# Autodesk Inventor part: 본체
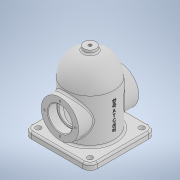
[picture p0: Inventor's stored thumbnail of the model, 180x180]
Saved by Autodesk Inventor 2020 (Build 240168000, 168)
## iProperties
Created: 2021-07
Part Number: 본체
Material: 일반
Document SubType Name: Modeling
Designer: Owner
Density: 1 g/cm^3
Appearance: 기본값
Author: Owner
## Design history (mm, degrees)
sketch "스케치1"
  geometry: C1 r 40 at (0, 0); 1 further point
  constraints: 1 centre point, 1 coincident
  dimensions: "d0" = 80 diameter of C1
extrude "돌출1" new body sketch "스케치1" distance "d1" = 124; taper "d2" = 0 deg
fillet "모깎기1" dims "d3" = 40
feature "쉘1" dims "d4" = 8
node "작업 평면1"
sketch "스케치3"
  geometry: C1 r 31 at (0, 48); 1 further point
  constraints: 1 centre point, 1 vertical alignment
  dimensions: "d6" = 62 diameter of C1; "d7" = 48 distance of point (0, 0) C1.centre
extrude "돌출2" join sketch "스케치3" stored distance "d8" = 124; taper "d9" = 0 deg
sketch "스케치4"
  geometry: C1 r 31 at (0, 0) reference; 2 further points
  constraints: 1 coincident
hole "구멍1" sketch "스케치4" at (0, 0) diameter "d10" = 33; stored, may be unused: countersink angle "d14" = 90 deg, drill point angle "d16" = 0 deg; dims "d11" = 6, "d12" = 40, "d13" = 15, "d15" = 8
sketch "스케치5"
  geometry: C1 r 31 at (0, 0) reference; 2 further points
  constraints: 1 vertical alignment
  dimensions: "d17" = 25.5 distance of C1.centre point (0, 25.5)
hole "구멍2" sketch "스케치5" at (0, 25.5) diameter "d18" = 3.242; stored, may be unused: countersink angle "d22" = 90 deg, drill point angle "d24" = 118 deg; dims "d19" = 8, "d20" = 40, "d21" = 15, "d23" = 10
node "작업 평면2"
sketch "스케치6"
  geometry: L1 (0, -40)-(0, 40) reference; 2 further points
  constraints: 1 horizontal alignment, 1 other
  dimensions: "d28" = 48 distance from line of L1 point (48, 0)
feature "엠보싱1" sketch "스케치6" dims "d29" = 0.5, "d30" = 0
sketch "스케치7"
  geometry: L1 (-55, -55)-(55, -55); L2 (55, -55)-(55, 55); L3 (55, 55)-(-55, 55); L4 (-55, 55)-(-55, -55); L5 (-55, -55)-(55, 55); L6 (55, -55)-(-55, 55); C1 r 40 at (0, 0) reference; 1 further point
  constraints: 12 end point, 2 midpoint, 2 parallel, 1 horizontal, 1 perpendicular
  dimensions: "d31" = 110 distance of L1.end L2.end; "d32" = 110 distance of L1.start L1.end
extrude "돌출3" join sketch "스케치7" distance "d33" = 10; taper "d34" = 0 deg
fillet "모깎기2" dims "d35" = 12
sketch "스케치8"
  geometry: A1 r 12 centre (43, -43) between (43, -55) and (55, -43) reference; 2 further points
  constraints: 1 coincident
hole "구멍3" sketch "스케치8" at (43, -43) diameter "d36" = 9; stored, may be unused: countersink angle "d40" = 90 deg, drill point angle "d42" = 118 deg; dims "d37" = 8, "d38" = 40, "d39" = 15, "d41" = 10
sketch "스케치9"
  geometry: A1 r 12 centre (-43, -43) between (-55, -43) and (-43, -55) reference; 2 further points
  constraints: 1 coincident
hole "구멍4" sketch "스케치9" at (-43, -43) diameter "d43" = 9; stored, may be unused: countersink angle "d47" = 90 deg, drill point angle "d49" = 118 deg; dims "d44" = 8, "d45" = 40, "d46" = 15, "d48" = 10
node "작업 평면3"
sketch "스케치10"
  geometry: C1 r 32 at (0, 0) reference; C2 r 10 at (0, 0); 1 further point
  constraints: 1 centre point, 1 coincident
  dimensions: "d51" = 20 diameter of C2
extrude "돌출4" join sketch "스케치10" stored distance "d52" = 10; taper "d53" = 0 deg
sketch "스케치11"
  geometry: C1 r 10 at (0, 0) reference; 2 further points
  constraints: 1 coincident
hole "구멍5" sketch "스케치11" at (0, 0) diameter "d54" = 5.1881; stored, may be unused: countersink angle "d58" = 90 deg, drill point angle "d60" = 118 deg; dims "d55" = 12, "d56" = 40, "d57" = 15, "d59" = 16
fillet "모깎기3" dims "d61" = 0.3
fillet "모깎기4" dims "d62" = 3
chamfer "모따기1" distance "d63" = 1; stored, may be unused: second distance "d64" = 2, angle "d65" = 45 deg
node "솔리드1"
pattern_circular "원형 패턴1" dims angle "d26" = 360 deg
mirror "미러1"
mirror "미러2"
feature "A9D066F2-1C7D-4E18-AEED-F7BC21143FA4" dims "d10" = 33, "d11" = 6, "d12" = 40, "d13" = 15, "d14" = 90 deg, "d15" = 8, "d16" = 0
other parameters: "d50" = 129
